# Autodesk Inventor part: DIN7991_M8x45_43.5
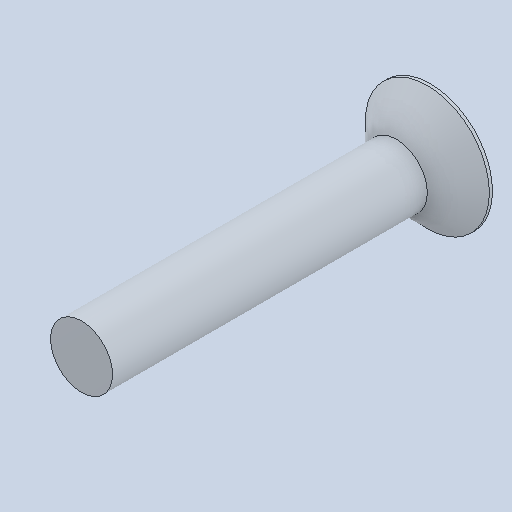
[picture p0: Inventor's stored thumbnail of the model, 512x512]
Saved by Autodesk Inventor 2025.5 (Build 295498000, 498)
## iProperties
Created: 2026-10
Part Number: DIN7991_M8x45_43.5
Material: Genérico
Document SubType Name: Modeling
Designer: Luis M
Density: 1 g/cm^3
Appearance: Valor por defecto
Author: Luis M
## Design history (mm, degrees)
feature "Base1"
node "Sólido1"
